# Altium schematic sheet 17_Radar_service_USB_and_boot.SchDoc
size 289 x 400 mm
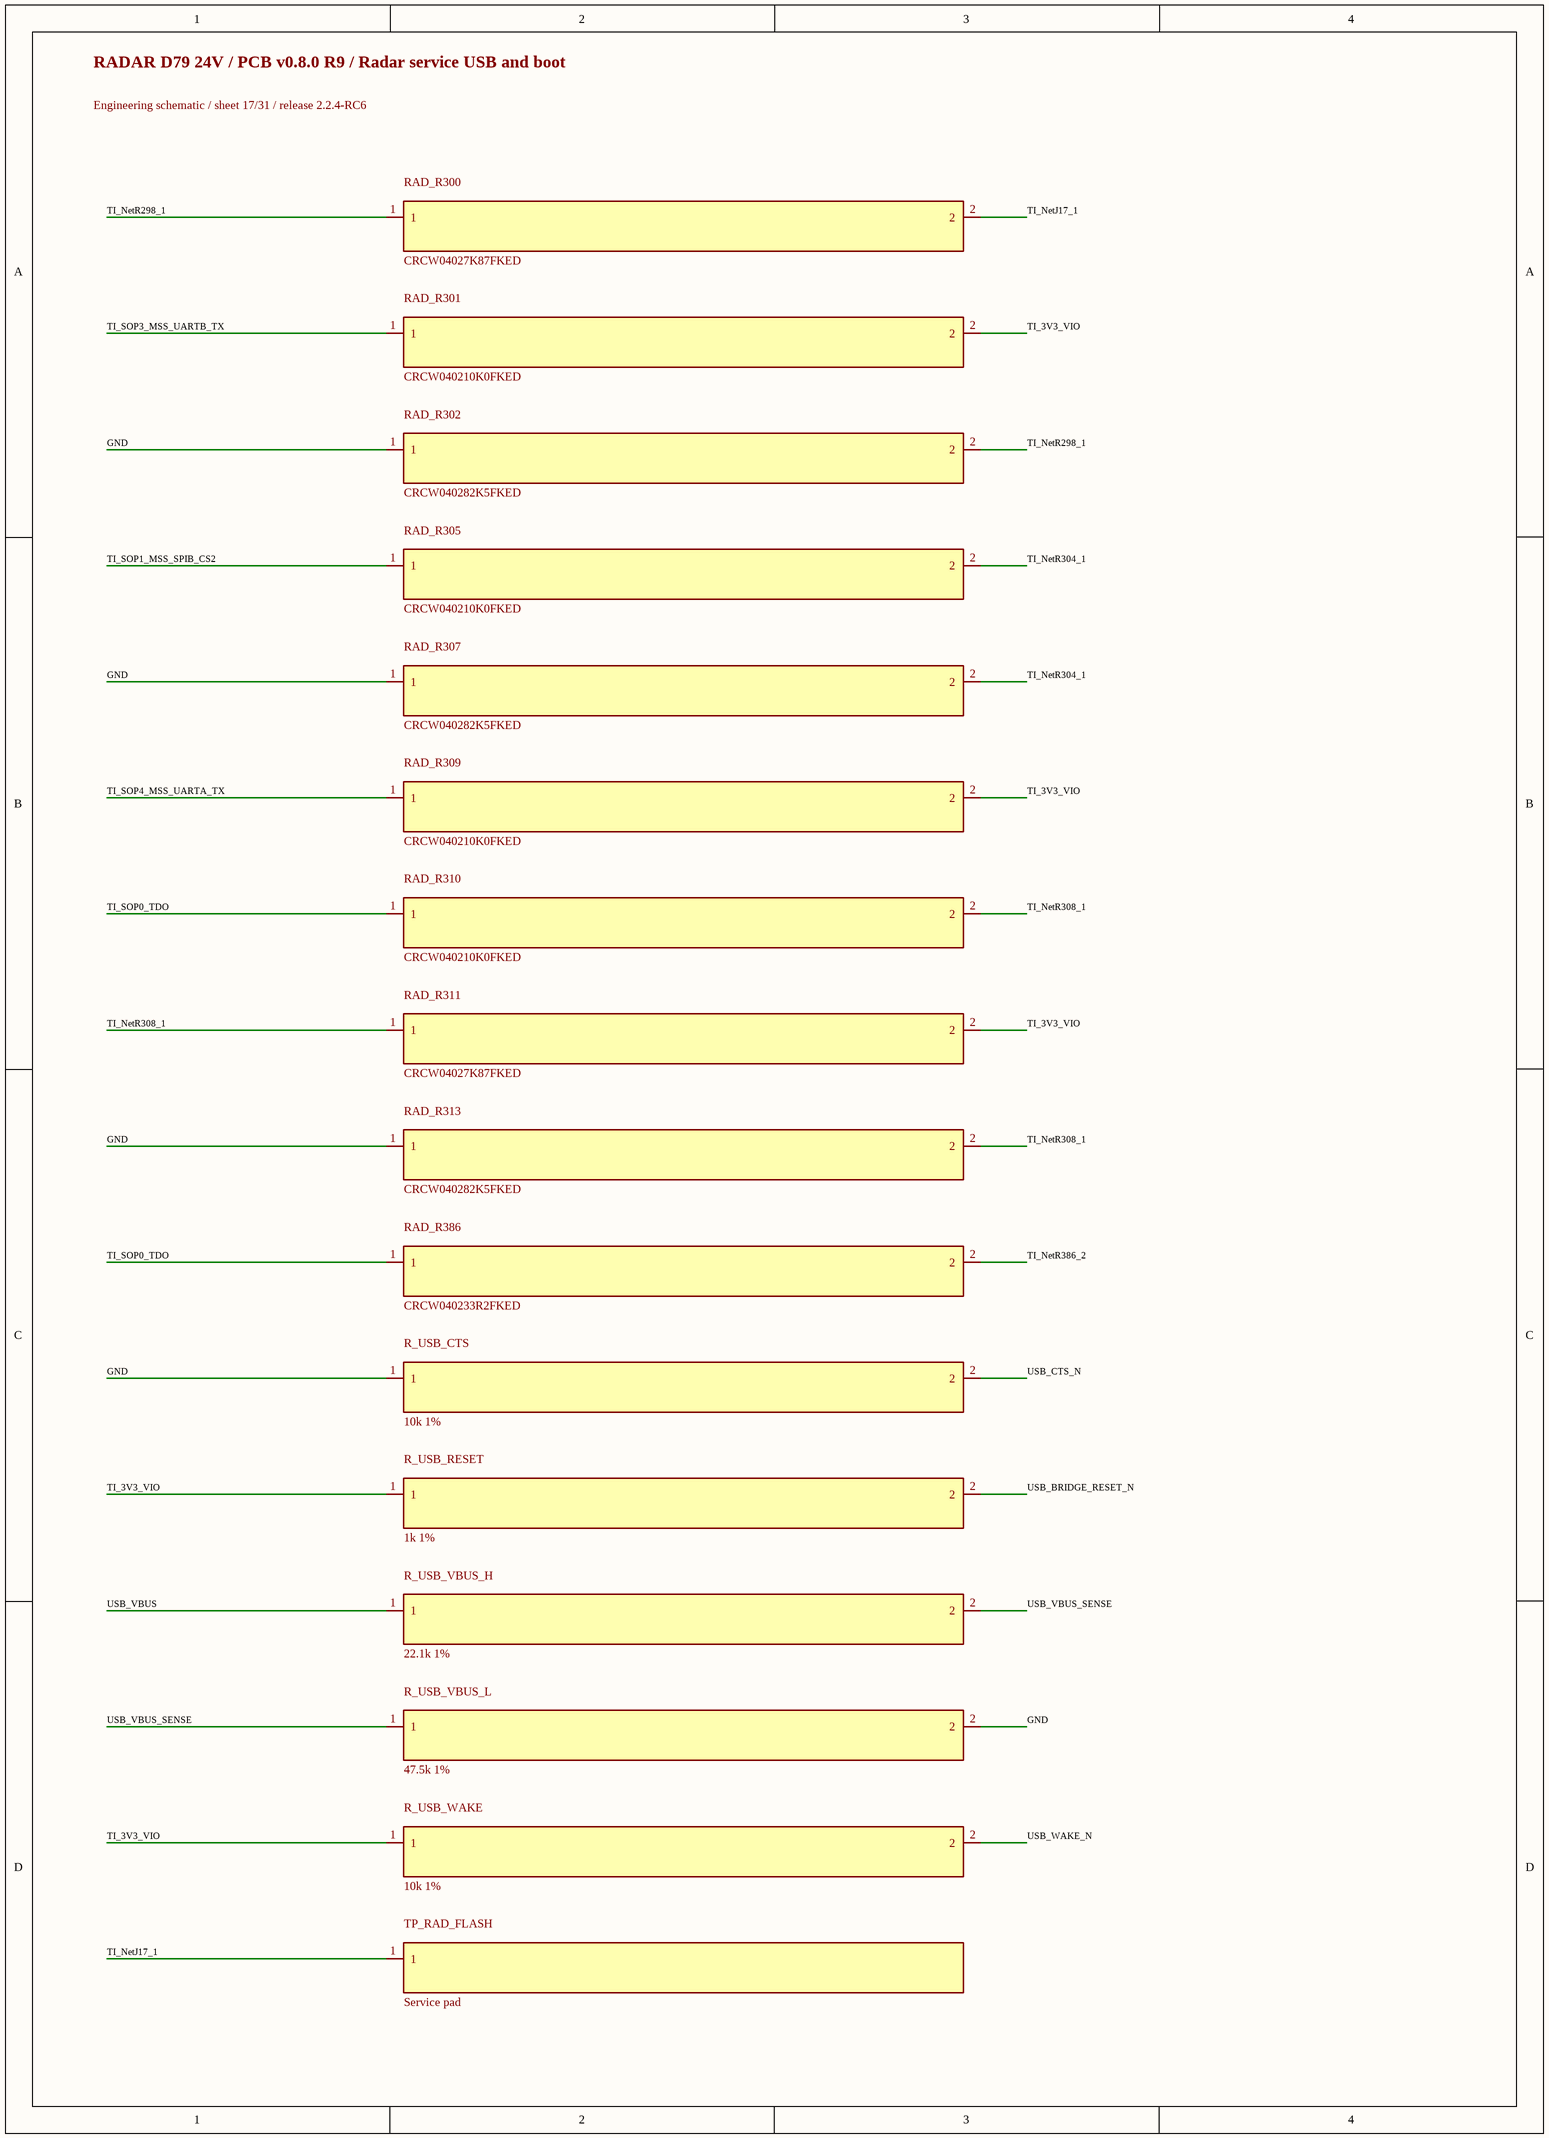
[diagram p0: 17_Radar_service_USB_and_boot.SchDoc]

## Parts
R_USB_CTS  10k 1%  [R_0402_1005Metric]
R_USB_RESET  1k 1%  [R_0402_1005Metric]
R_USB_VBUS_H  22.1k 1%  [R_0402_1005Metric]
R_USB_VBUS_L  47.5k 1%  [R_0402_1005Metric]
R_USB_WAKE  10k 1%  [R_0402_1005Metric]
RAD_R300  CRCW04027K87FKED  [0402L]
RAD_R301  CRCW040210K0FKED  [0402L]
RAD_R302  CRCW040282K5FKED  [0402L]
RAD_R305  CRCW040210K0FKED  [0402L]
RAD_R307  CRCW040282K5FKED  [0402L]
RAD_R309  CRCW040210K0FKED  [0402L]
RAD_R310  CRCW040210K0FKED  [0402L]
RAD_R311  CRCW04027K87FKED  [0402L]
RAD_R313  CRCW040282K5FKED  [0402L]
RAD_R386  CRCW040233R2FKED  [0402L]
TP_RAD_FLASH  Service pad  [TestPoint_Pad_D1.5mm]

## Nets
GND: R_USB_CTS.1 R_USB_VBUS_L.2 RAD_R302.1 RAD_R307.1 RAD_R313.1
TI_3V3_VIO: R_USB_RESET.1 R_USB_WAKE.1 RAD_R301.2 RAD_R309.2 RAD_R311.2
TI_NetJ17_1: RAD_R300.2 TP_RAD_FLASH.1
TI_NetR298_1: RAD_R300.1 RAD_R302.2
TI_NetR304_1: RAD_R305.2 RAD_R307.2
TI_NetR308_1: RAD_R310.2 RAD_R311.1 RAD_R313.2
TI_NetR386_2: RAD_R386.2
TI_SOP0_TDO: RAD_R310.1 RAD_R386.1
TI_SOP1_MSS_SPIB_CS2: RAD_R305.1
TI_SOP3_MSS_UARTB_TX: RAD_R301.1
TI_SOP4_MSS_UARTA_TX: RAD_R309.1
USB_BRIDGE_RESET_N: R_USB_RESET.2
USB_CTS_N: R_USB_CTS.2
USB_VBUS: R_USB_VBUS_H.1
USB_VBUS_SENSE: R_USB_VBUS_H.2 R_USB_VBUS_L.1
USB_WAKE_N: R_USB_WAKE.2

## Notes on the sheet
- RADAR D79 24V / PCB v0.8.0 R9 / Radar service USB and boot
- Engineering schematic / sheet 17/31 / release 2.2.4-RC6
